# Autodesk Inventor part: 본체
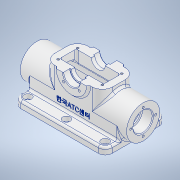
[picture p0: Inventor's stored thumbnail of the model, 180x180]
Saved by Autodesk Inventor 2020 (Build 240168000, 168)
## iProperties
Created: 2024-06
Part Number: 본체
Material: 알루미늄 6061
Document SubType Name: Modeling
Designer: oem
Density: 2.7 g/cm^3
Appearance: 알루미늄 - 평지
Mass: 547.734 g
Surface Area: 611.725 cm^2
Volume: 202.864 cm^3
Author: oem
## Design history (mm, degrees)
sketch "스케치2"
  geometry: L1 (42, 24)-(-42, 24); L2 (-42, 24)-(-42, -24); L3 (-42, -24)-(42, -24); L4 (42, -24)-(42, 24); L5 (42, 24)-(-42, -24); L6 (-42, 24)-(42, -24); 1 further point
  constraints: 12 end point, 2 midpoint, 2 parallel, 1 horizontal, 1 perpendicular
  dimensions: "d0" = 48 distance between parallel lines of L1 L3; "d1" = 84 distance between parallel lines of L2 L4
extrude "돌출1" new body sketch "스케치2" distance "d2" = 59; taper "d3" = 0 deg
fillet "모깎기1" dims "d4" = 15
node "작업 평면1"
sketch "스케치6"
  geometry: L1 (-27, 59)-(27, 59) reference; C1 r 22 at (0, 59); 3 further points
  constraints: 1 centre point, 1 midpoint
  dimensions: "d14" = 44 diameter of C1
extrude "돌출2" join sketch "스케치6" distance "d15" = 54; taper "d16" = 0 deg
sketch "스케치8"
  geometry: L1 (-22, 27)-(22, 27) reference; L2 (22, -27)-(-22, -27) reference; L3 (0, 27)-(0, -27); L4 (-12, 27)-(-12, 17); L5 (-12, 17)-(-10, 17); L6 (-10, 17)-(-10, -17); L7 (-10, -17)-(-12, -17); L8 (-12, -17)-(-12, -27); L9 (-22, -27)-(22, -27) reference; 2 further points
  constraints: 12 end point, 4 perpendicular, 3 point on line, 2 midpoint, 1 vertical
  dimensions: "d17" = 24 diameter of L4 L3; "d18" = 20 diameter of L6 L3; "d19" = 10 distance between parallel lines of L5 L1; "d20" = 10 distance between parallel lines of L7 L2
revolve "회전1" sketch "스케치8" stored, may be unused: angle "d21" = 180 deg
chamfer "모따기1" distance "d22" = 1; stored, may be unused: second distance "d23" = 2, angle "d24" = 45 deg
node "작업 평면2"
sketch "스케치10"
  geometry: L1 (-66, -44)-(66, -44); L2 (66, -44)-(66, 44); L3 (66, 44)-(-66, 44); L4 (-66, 44)-(-66, -44); L5 (-66, -44)-(66, 44); L6 (66, -44)-(-66, 44); 1 further point
  constraints: 12 end point, 2 midpoint, 2 parallel, 1 horizontal, 1 perpendicular
  dimensions: "d26" = 132 distance of L3.end L2.end; "d27" = 88 distance between parallel lines of L1 L3
extrude "돌출3" join sketch "스케치10" distance "d28" = 10; taper "d29" = 0 deg
fillet "모깎기2" dims "d30" = 10
sketch "스케치11"
  geometry: L1 (46, 27)-(47, 26) reference; L2 (47, 26)-(47, 17) reference; L3 (47, 17)-(49, 17) reference; L4 (49, 17)-(49, -17) reference; L5 (49, -17)-(47, -17) reference; L6 (47, -17)-(47, -26) reference; L7 (47, -26)-(46, -27) reference; L8 (46, -27)-(37, -27) reference; L9 (37, -27)-(37, -24) reference; L10 (37, -24)-(10, -24) reference; L11 (10, -24)-(10, -44) reference; L12 (10, -44)-(0, -44) reference; L13 (0, -44)-(0, 44) reference; L14 (0, 44)-(10, 44) reference; L15 (10, 44)-(10, 24) reference; L16 (10, 24)-(37, 24) reference; L17 (37, 24)-(37, 27) reference; L18 (37, 27)-(46, 27) reference; C1 r 24 at (28, 0); 2 further points
  constraints: 1 centre point, 1 horizontal alignment, 1 midpoint
  dimensions: "d31" = 48 diameter of C1; "d33" = 28 distance of point (0, 0) C1.centre
extrude "돌출4" join sketch "스케치11" stored distance "d34" = 154; taper "d35" = 0 deg
sketch "스케치12"
  geometry: L1 (-32, -12)-(32, -12); L2 (32, -12)-(32, 12); L3 (32, 12)-(-32, 12); L4 (-32, 12)-(-32, -12); L5 (-32, -12)-(32, 12); L6 (32, -12)-(-32, 12); 1 further point
  constraints: 12 end point, 2 midpoint, 2 parallel, 1 horizontal, 1 perpendicular
  dimensions: "d36" = 64 distance between parallel lines of L2 L4; "d37" = 24 distance between parallel lines of L1 L3
extrude "돌출5" cut sketch "스케치12" stored distance "d38" = 10; taper "d39" = 0 deg
fillet "모깎기3" dims "d40" = 3
sketch "스케치13"
  geometry: L1 (-66, 4)-(-77, 4) reference; L2 (-77, 4)-(-77, 52) reference; L3 (-77, 52)-(-42, 52) reference; L4 (-42, 52)-(-42, 59) reference; L5 (-42, 59)-(-32, 59) reference; L6 (-32, 59)-(-32, 0) reference; L7 (-32, 0)-(-66, 0) reference; L8 (-66, 0)-(-66, 4) reference; L9 (77, 4)-(66, 4) reference; L10 (66, 4)-(66, 0) reference; L11 (66, 0)-(32, 0) reference; L12 (32, 0)-(32, 59) reference; L13 (32, 59)-(42, 59) reference; L14 (42, 59)-(42, 52) reference; L15 (42, 52)-(77, 52) reference; L16 (77, 52)-(77, 4) reference; L17 (-77, 52)-(-77, 4) reference; L18 (-77, 28)-(77, 28); L19 (77, 4)-(77, 52) reference; L20 (-62, 42)-(-62, 39); L21 (-62, 39)-(-60, 39); L22 (-60, 39)-(-60, 46); L23 (-60, 46)-(60, 46); L24 (60, 46)-(60, 39); L25 (60, 39)-(62, 39); L26 (62, 39)-(62, 42); L27 (62, 42)-(77, 42); L28 (-62, 42)-(-77, 42); 6 further points
  constraints: 20 end point, 7 perpendicular, 4 point on line, 3 midpoint, 1 vertical, 1 vertical alignment
  dimensions: "d41" = 28 distance between parallel lines of L7 L18; "d43" = 15 distance of L20.start L28.end; "d44" = 28 diameter of L28 L18; "d45" = 22 diameter of L21 L18; "d46" = 36 diameter of L23 L18; "d47" = 15 distance of L26.end L27.end; "d48" = 28 diameter of L27 L18; "d50" = 120 distance between parallel lines of L24 L22
revolve "회전2" sketch "스케치13" stored, may be unused: angle "d51" = 90 deg
chamfer "모따기2" distance "d54" = 1; stored, may be unused: second distance "d55" = 2, angle "d56" = 45 deg
fillet "모깎기4" dims "d57" = 3
sketch "스케치16"
  geometry: L1 (0, 0)-(0, 18) reference; L2 (54, 18)-(54, 0) reference; L3 (-29, 0)-(83, 0) reference; L4 (-29, -10)-(-29, 0) reference; L5 (93, 0)-(67.332, 0) reference; L6 (93, 0)-(93, -6) reference; L7 (83, 0)-(-29, 0) reference; L8 (83, -10)-(-29, -10) reference; L9 (27, -21.8)-(27, 60.8) reference; L10 (54, 18)-(54, 49); L11 (-39, 0)-(0, 0) reference; L12 (0, 0)-(54, 0) reference; L13 (54, 0)-(93, 0) reference; L14 (93, 0)-(93, -10) reference; L15 (93, -10)-(-39, -10) reference; L16 (-39, -10)-(-39, 0) reference; L17 (0, 0)-(0, 18) reference; L18 (0, 18)-(0, 49) reference; L19 (0, 49)-(2, 49) reference; L20 (39, 49)-(52, 49) reference; L21 (2, 49)-(15, 49) reference; L22 (54, 0)-(54, 18) reference; L23 (54, 18)-(104, 18) reference; L24 (-50, 18)-(0, 18) reference; L25 (52, 49)-(54, 49) reference; L26 (54, 18)-(54, 49) reference; L27 (0, 49)-(0, 18); L28 (0, 18)-(-39, 18); L29 (-33, 36)-(-33, 0) reference; L30 (-39, 18)-(-39, 0); L31 (54, 18)-(54, 49); L32 (54, 18)-(93, 18); L33 (93, 18)-(93, 0); A1 r 25 centre (27, 49) between (2, 49) and (52, 49) reference; A2 r 12 centre (27, 49) between (15, 49) and (39, 49) reference; 3 further points
  constraints: 14 end point, 3 symmetric about line, 2 perpendicular, 2 point on line
  dimensions: "d61" = 28 distance between parallel lines of L8 L28
extrude "돌출7" join sketch "스케치16" stored distance "d59" = 120; taper "d60" = 0 deg
sketch "스케치14"
  geometry: L1 (47, -26)-(46, -27) reference; L2 (46, -27)-(37, -27) reference; L3 (34, -24)-(10, -24) reference; L4 (10, -24)-(10, -44) reference; L5 (10, -44)-(0, -44) reference; L6 (0, -44)-(0, -12) reference; L7 (0, -12)-(14.584, -12) reference; L8 (41.416, -12)-(49, -12) reference; L9 (49, -12)-(49, -17) reference; L10 (49, -17)-(47, -17) reference; L11 (47, -17)-(47, -26) reference; L12 (46, 27)-(47, 26) reference; L13 (47, 26)-(47, 17) reference; L14 (47, 17)-(49, 17) reference; L15 (49, 17)-(49, 12) reference; L16 (49, 12)-(41.416, 12) reference; L17 (14.584, 12)-(0, 12) reference; L18 (0, 12)-(0, 44) reference; L19 (0, 44)-(10, 44) reference; L20 (10, 44)-(10, 24) reference; L21 (10, 24)-(34, 24) reference; L22 (37, 27)-(46, 27) reference; L23 (28, 18)-(0, 18); L24 (0, -34)-(0, 34) reference; L25 (28, -18)-(0, -18); L26 (0, 18)-(0, -18); A1 r 18 centre (28, 0) between (14.584, -12) and (41.416, -12) reference; A2 r 18 centre (28, 0) between (41.416, 12) and (14.584, 12) reference; A3 r 18 centre (28, 0) between (14.584, -12) and (41.416, -12) reference; A4 r 3 centre (34, -27) between (37, -27) and (34, -24) reference; A5 r 3 centre (34, 27) between (34, 24) and (37, 27) reference; 2 further points
  constraints: 6 end point, 3 point on circle, 2 perpendicular, 2 point on line, 1 collinear
extrude "돌출8" cut sketch "스케치14" stored distance "d62" = 120; taper "d63" = 0 deg
sketch "스케치18"
  geometry: L1 (-32, -14)-(32, -14); L2 (32, -14)-(32, 14); L3 (32, 14)-(-32, 14); L4 (-32, 14)-(-32, -14); L5 (-32, -14)-(32, 14); L6 (32, -14)-(-32, 14); 5 further points
  constraints: 12 end point, 4 coincident, 2 midpoint, 2 parallel, 1 horizontal, 1 perpendicular
  dimensions: "d64" = 64 distance between parallel lines of L2 L4; "d65" = 28 distance between parallel lines of L1 L3
hole "구멍1" sketch "스케치18" at (-32, 14), (32, 14), (32, -14), (-32, -14) diameter "d66" = 3.242; stored, may be unused: countersink angle "d70" = 90 deg, drill point angle "d72" = 118 deg; dims "d67" = 8, "d68" = 7, "d69" = 2, "d71" = 10
sketch "스케치19" dims "d73" = 32
  geometry: L1 (0, 59)-(0, 37); L2 (0, 59)-(15.556, 43.444); A1 r 22 centre (0, 59) between (-22, 59) and (22, 59) reference; A2 r 22 centre (0, 59) between (-22, 59) and (22, 59) reference; 2 further points
  constraints: 4 end point, 3 point on circle, 1 coincident, 1 point on line, 3 other
  dimensions: "d74" = 45 deg angle of L2 L1
hole "구멍2" sketch "스케치19" at (11.314, 47.686) diameter "d75" = 3.242; stored, may be unused: countersink angle "d79" = 90 deg, drill point angle "d81" = 118 deg; dims "d76" = 8, "d77" = 7, "d78" = 2, "d80" = 10
sketch "스케치20"
  geometry: C1 r 15 at (0, 0) reference; A1 r 18 centre (0, 0) between (9, 15.588) and (-9, 15.588); A2 r 18 centre (0, 0) between (9, 15.588) and (-9, 15.588) reference; 2 further points
  constraints: 1 centre point, 1 coincident, 1 point on circle
  dimensions: "d82" = 36 diameter of A1
hole "구멍3" sketch "스케치20" at (0, 18) diameter "d83" = 3.242; stored, may be unused: countersink angle "d87" = 90 deg, drill point angle "d89" = 118 deg; dims "d84" = 8, "d85" = 7, "d86" = 2, "d88" = 10
sketch "스케치21"
  geometry: C1 r 15 at (0, 0) reference; A1 r 18 centre (0, 0) between (9, 15.588) and (-9, 15.588); A2 r 18 centre (0, 0) between (9, 15.588) and (-9, 15.588) reference; 2 further points
  constraints: 1 centre point, 1 coincident, 1 point on circle
  dimensions: "d93" = 36 diameter of A1
hole "구멍4" sketch "스케치21" at (0, 18) diameter "d94" = 3.242; stored, may be unused: countersink angle "d98" = 90 deg, drill point angle "d100" = 118 deg; dims "d95" = 8, "d96" = 7, "d97" = 2, "d99" = 10
sketch "스케치23"
  geometry: A1 r 10 centre (56, 34) between (66, 34) and (56, 44) reference; 2 further points
  constraints: 1 coincident
hole "구멍5" sketch "스케치23" at (56, 34) diameter "d104" = 6.6; stored, may be unused: countersink angle "d108" = 90 deg, drill point angle "d110" = 0 deg; dims "d105" = 8, "d106" = 11, "d107" = 6.6, "d109" = 10
fillet "모깎기5" dims "d114" = 3
fillet "모깎기6" dims "d115" = 3
sketch "스케치24"
  geometry: L1 (-56, -59)-(56, -59) reference; A1 r 25 centre (0, 0) between (-25, 0) and (25, 0) reference; 2 further points
  constraints: 1 vertical alignment, 1 other
  dimensions: "d116" = 20 distance from line of L1 point (0, -39)
feature "엠보싱1" sketch "스케치24" dims "d117" = 0.5, "d118" = 0
fillet "모깎기7" dims "d119" = 0.3
node "솔리드1"
mirror "미러1"
mirror "미러2"
mirror "미러3"
pattern_circular "원형 패턴1" dims angle "d91" = 360 deg
pattern_circular "원형 패턴2" dims angle "d102" = 360 deg
pattern_linear "직사각형 패턴1" dims "d113" = 56
mirror "미러4"
node "절단 모서리 투영2"
node "절단 모서리 투영3"
node "절단 모서리 투영4"
node "절단 모서리 투영6"
feature "A9D066F2-1C7D-4E18-AEED-F7BC21143FA4" dims "d66" = 3.242, "d67" = 8, "d68" = 7, "d69" = 2, "d70" = 90 deg, "d71" = 10, "d72" = 118 deg
other parameters: "d13" = 27, "d25" = -59
